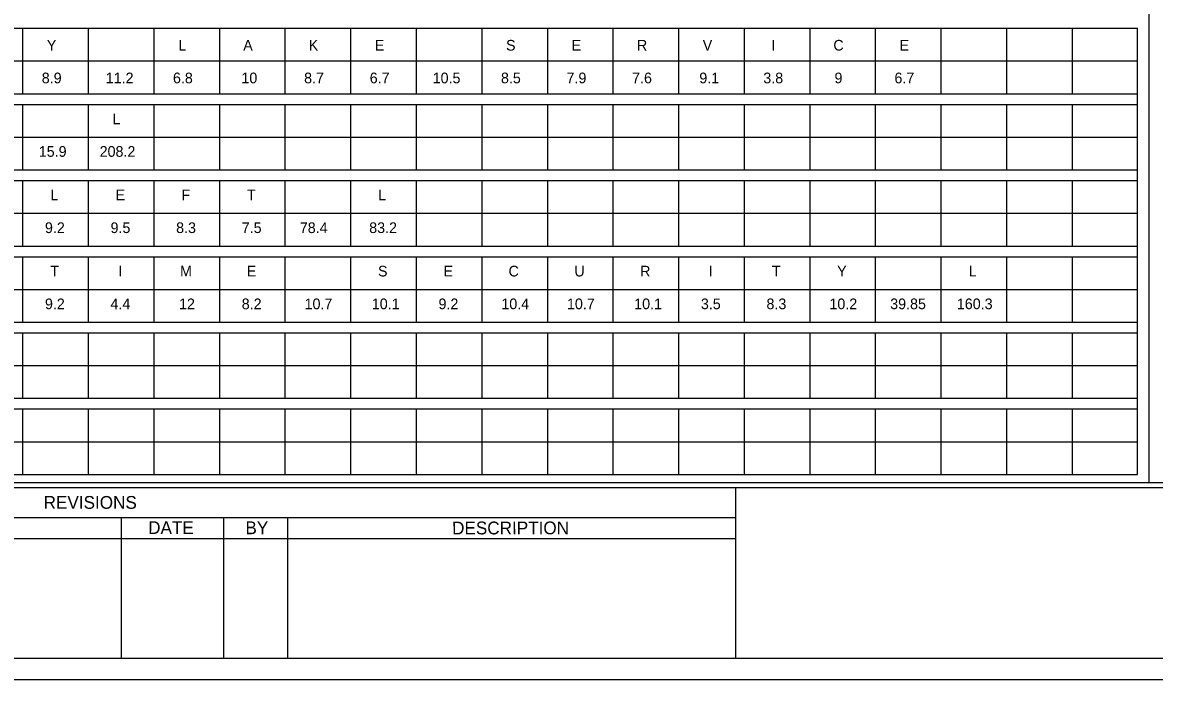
# Model space of a CAD drawing. Extents: x 17890071 to 17890754, y 17897628 to 17897992.
# Drawn here: x 17890100.2 to 17890152.1, y 17897766.7 to 17897796.9 of the extents above; entities that cross this region are included whole.
import ezdxf

# ---------------------------------------------------------------- set-up
doc = ezdxf.new("R2010")
doc.units = 0
for name, color, linetype in [('GSSign', 7, 'Continuous'), ('PlotBorder_dp', 7, 'Continuous'), ('SheetBorder_dp', 7, 'Continuous'), ('SheetLines_dp', 7, 'Continuous'), ('SheetLinesMisc2_dp', 7, 'Continuous'), ('TextMisc', 7, 'Continuous')]:
    doc.layers.add(name, color=color, linetype=linetype)

msp = doc.modelspace()

# ---------------------------------------------------------------- linework, layer by layer
at = {"layer": 'PlotBorder_dp'}
msp.add_lwpolyline([(17890071.13, 17897766.734), (17890232.646, 17897766.734), (17890232.646, 17897870.495), (17890071.13, 17897870.495)], close=True, dxfattribs=at)
at = {"layer": 'SheetBorder_dp'}
for p, q in [((17890076.514, 17897775.543), (17890227.262, 17897775.543)), ((17890076.514, 17897767.712), (17890227.262, 17897767.712))]:
    msp.add_line(p, q, dxfattribs=at)
at = {"layer": 'SheetLines_dp'}
for p, q in [((17890132.897, 17897775.543), (17890132.897, 17897767.712)), ((17890076.514, 17897774.173), (17890132.897, 17897774.173)), ((17890104.706, 17897774.173), (17890104.706, 17897767.712)), ((17890109.404, 17897774.173), (17890109.404, 17897767.712)), ((17890112.341, 17897774.173), (17890112.341, 17897767.712)), ((17890076.514, 17897773.194), (17890132.897, 17897773.194))]:
    msp.add_line(p, q, dxfattribs=at)
at = {"layer": 'SheetLinesMisc2_dp'}
for p, q in [((17890151.871, 17897869.435), (17890151.871, 17897775.777)), ((17890077.364, 17897796.631), (17890151.359, 17897796.631)), ((17890100.188, 17897796.631), (17890100.188, 17897793.624)), ((17890103.198, 17897796.631), (17890103.198, 17897793.624)), ((17890106.208, 17897796.631), (17890106.208, 17897793.624)), ((17890109.218, 17897796.631), (17890109.218, 17897793.624)), ((17890112.228, 17897796.631), (17890112.228, 17897793.624)), ((17890115.238, 17897796.631), (17890115.238, 17897793.624)), ((17890118.248, 17897796.631), (17890118.248, 17897793.624)), ((17890121.258, 17897796.631), (17890121.258, 17897793.624)), ((17890124.269, 17897796.631), (17890124.269, 17897793.624)), ((17890127.279, 17897796.631), (17890127.279, 17897793.624)), ((17890130.289, 17897796.631), (17890130.289, 17897793.624)), ((17890133.299, 17897796.631), (17890133.299, 17897793.624)), ((17890136.309, 17897796.631), (17890136.309, 17897793.624)), ((17890139.319, 17897796.631), (17890139.319, 17897793.624)), ((17890142.329, 17897796.631), (17890142.329, 17897793.624)), ((17890145.339, 17897796.631), (17890145.339, 17897793.624)), ((17890148.35, 17897796.631), (17890148.35, 17897793.624)), ((17890151.359, 17897776.142), (17890151.359, 17897796.631)), ((17890077.364, 17897795.129), (17890151.359, 17897795.129)), ((17890077.364, 17897793.624), (17890151.359, 17897793.624)), ((17890077.364, 17897793.134), (17890151.359, 17897793.134)), ((17890100.188, 17897793.134), (17890100.188, 17897790.128)), ((17890103.198, 17897793.134), (17890103.198, 17897790.128)), ((17890106.208, 17897793.134), (17890106.208, 17897790.128)), ((17890109.218, 17897793.134), (17890109.218, 17897790.128)), ((17890112.228, 17897793.134), (17890112.228, 17897790.128)), ((17890115.238, 17897793.134), (17890115.238, 17897790.128)), ((17890118.248, 17897793.134), (17890118.248, 17897790.128)), ((17890121.258, 17897793.134), (17890121.258, 17897790.128)), ((17890124.269, 17897793.134), (17890124.269, 17897790.128)), ((17890127.279, 17897793.134), (17890127.279, 17897790.128)), ((17890130.289, 17897793.134), (17890130.289, 17897790.128)), ((17890133.299, 17897793.134), (17890133.299, 17897790.128)), ((17890136.309, 17897793.134), (17890136.309, 17897790.128)), ((17890139.319, 17897793.134), (17890139.319, 17897790.128)), ((17890142.329, 17897793.134), (17890142.329, 17897790.128)), ((17890145.339, 17897793.134), (17890145.339, 17897790.128)), ((17890148.35, 17897793.134), (17890148.35, 17897790.128)), ((17890077.364, 17897791.631), (17890151.359, 17897791.631)), ((17890077.364, 17897790.128), (17890151.359, 17897790.128)), ((17890077.364, 17897789.637), (17890151.359, 17897789.637)), ((17890100.188, 17897789.637), (17890100.188, 17897786.631)), ((17890103.198, 17897789.637), (17890103.198, 17897786.631)), ((17890106.208, 17897789.637), (17890106.208, 17897786.631)), ((17890109.218, 17897789.637), (17890109.218, 17897786.631)), ((17890112.228, 17897789.637), (17890112.228, 17897786.631)), ((17890115.238, 17897789.637), (17890115.238, 17897786.631)), ((17890118.248, 17897789.637), (17890118.248, 17897786.631)), ((17890121.258, 17897789.637), (17890121.258, 17897786.631)), ((17890124.269, 17897789.637), (17890124.269, 17897786.631)), ((17890127.279, 17897789.637), (17890127.279, 17897786.631)), ((17890130.289, 17897789.637), (17890130.289, 17897786.631)), ((17890133.299, 17897789.637), (17890133.299, 17897786.631)), ((17890136.309, 17897789.637), (17890136.309, 17897786.631)), ((17890139.319, 17897789.637), (17890139.319, 17897786.631)), ((17890142.329, 17897789.637), (17890142.329, 17897786.631)), ((17890145.339, 17897789.637), (17890145.339, 17897786.631)), ((17890148.35, 17897789.637), (17890148.35, 17897786.631)), ((17890077.364, 17897788.135), (17890151.359, 17897788.135)), ((17890077.364, 17897786.631), (17890151.359, 17897786.631)), ((17890077.364, 17897786.141), (17890151.359, 17897786.141)), ((17890100.188, 17897786.141), (17890100.188, 17897783.135)), ((17890103.198, 17897786.141), (17890103.198, 17897783.135)), ((17890106.208, 17897786.141), (17890106.208, 17897783.135)), ((17890109.218, 17897786.141), (17890109.218, 17897783.135)), ((17890112.228, 17897786.141), (17890112.228, 17897783.135)), ((17890115.238, 17897786.141), (17890115.238, 17897783.135)), ((17890118.248, 17897786.141), (17890118.248, 17897783.135)), ((17890121.258, 17897786.141), (17890121.258, 17897783.135)), ((17890124.269, 17897786.141), (17890124.269, 17897783.135)), ((17890127.279, 17897786.141), (17890127.279, 17897783.135)), ((17890130.289, 17897786.141), (17890130.289, 17897783.135)), ((17890133.299, 17897786.141), (17890133.299, 17897783.135)), ((17890136.309, 17897786.141), (17890136.309, 17897783.135)), ((17890139.319, 17897786.141), (17890139.319, 17897783.135)), ((17890142.329, 17897786.141), (17890142.329, 17897783.135)), ((17890145.339, 17897786.141), (17890145.339, 17897783.135)), ((17890148.35, 17897786.141), (17890148.35, 17897783.135)), ((17890077.364, 17897784.639), (17890151.359, 17897784.639)), ((17890077.364, 17897783.135), (17890151.359, 17897783.135)), ((17890077.364, 17897782.644), (17890151.359, 17897782.644)), ((17890100.188, 17897782.644), (17890100.188, 17897779.638)), ((17890103.198, 17897782.644), (17890103.198, 17897779.638)), ((17890106.208, 17897782.644), (17890106.208, 17897779.638)), ((17890109.218, 17897782.644), (17890109.218, 17897779.638)), ((17890112.228, 17897782.644), (17890112.228, 17897779.638)), ((17890115.238, 17897782.644), (17890115.238, 17897779.638)), ((17890118.248, 17897782.644), (17890118.248, 17897779.638)), ((17890121.258, 17897782.644), (17890121.258, 17897779.638)), ((17890124.269, 17897782.644), (17890124.269, 17897779.638)), ((17890127.279, 17897782.644), (17890127.279, 17897779.638)), ((17890130.289, 17897782.644), (17890130.289, 17897779.638)), ((17890133.299, 17897782.644), (17890133.299, 17897779.638)), ((17890136.309, 17897782.644), (17890136.309, 17897779.638)), ((17890139.319, 17897782.644), (17890139.319, 17897779.638)), ((17890142.329, 17897782.644), (17890142.329, 17897779.638)), ((17890145.339, 17897782.644), (17890145.339, 17897779.638)), ((17890148.35, 17897782.644), (17890148.35, 17897779.638)), ((17890077.364, 17897781.141), (17890151.359, 17897781.141)), ((17890077.364, 17897779.638), (17890151.359, 17897779.638)), ((17890077.364, 17897779.148), (17890151.359, 17897779.148)), ((17890100.188, 17897779.148), (17890100.188, 17897776.142)), ((17890103.198, 17897779.148), (17890103.198, 17897776.142)), ((17890106.208, 17897779.148), (17890106.208, 17897776.142)), ((17890109.218, 17897779.148), (17890109.218, 17897776.142)), ((17890112.228, 17897779.148), (17890112.228, 17897776.142)), ((17890115.238, 17897779.148), (17890115.238, 17897776.142)), ((17890118.248, 17897779.148), (17890118.248, 17897776.142)), ((17890121.258, 17897779.148), (17890121.258, 17897776.142)), ((17890124.269, 17897779.148), (17890124.269, 17897776.142)), ((17890127.279, 17897779.148), (17890127.279, 17897776.142)), ((17890130.289, 17897779.148), (17890130.289, 17897776.142)), ((17890133.299, 17897779.148), (17890133.299, 17897776.142)), ((17890136.309, 17897779.148), (17890136.309, 17897776.142)), ((17890139.319, 17897779.148), (17890139.319, 17897776.142)), ((17890142.329, 17897779.148), (17890142.329, 17897776.142)), ((17890145.339, 17897779.148), (17890145.339, 17897776.142)), ((17890148.35, 17897779.148), (17890148.35, 17897776.142)), ((17890077.364, 17897777.645), (17890151.359, 17897777.645)), ((17890077.364, 17897776.142), (17890151.359, 17897776.142)), ((17890076.643, 17897775.777), (17890227.099, 17897775.777))]:
    msp.add_line(p, q, dxfattribs=at)

# ---------------------------------------------------------------- texts
at = {"layer": 'GSSign'}
for s, height, p in [('Y', 0.49, (17890101.298, 17897795.604)), ('L', 0.49, (17890107.335, 17897795.604)), ('A', 0.49, (17890110.312, 17897795.604)), ('K', 0.49, (17890113.317, 17897795.604)), ('E', 0.49, (17890116.351, 17897795.604)), ('S', 0.49, (17890122.373, 17897795.604)), ('E', 0.49, (17890125.382, 17897795.604)), ('R', 0.49, (17890128.381, 17897795.604)), ('V', 0.49, (17890131.401, 17897795.604)), ('I', 0.49, (17890134.545, 17897795.604)), ('C', 0.49, (17890137.396, 17897795.604)), ('E', 0.49, (17890140.434, 17897795.604)), ('8.9', 0.4902, (17890101.066, 17897794.102)), ('11.2', 0.4902, (17890104.001, 17897794.102)), ('6.8', 0.4902, (17890107.087, 17897794.102)), ('10', 0.4902, (17890110.228, 17897794.102)), ('8.7', 0.4902, (17890113.106, 17897794.102)), ('6.7', 0.4902, (17890116.117, 17897794.102)), ('10.5', 0.4902, (17890119.006, 17897794.102)), ('8.5', 0.4902, (17890122.14, 17897794.102)), ('7.9', 0.4902, (17890125.149, 17897794.102)), ('7.6', 0.4902, (17890128.158, 17897794.102)), ('9.1', 0.4902, (17890131.244, 17897794.102)), ('3.8', 0.4902, (17890134.18, 17897794.102)), ('9', 0.49, (17890137.447, 17897794.102)), ('6.7', 0.4902, (17890140.2, 17897794.102)), ('L', 0.49, (17890104.317, 17897792.225)), ('15.9', 0.4902, (17890100.929, 17897790.727)), ('208.2', 0.4902, (17890103.722, 17897790.727)), ('L', 0.49, (17890101.46, 17897788.729)), ('E', 0.49, (17890104.455, 17897788.729)), ('F', 0.49, (17890107.474, 17897788.729)), ('T', 0.49, (17890110.488, 17897788.729)), ('L', 0.49, (17890116.512, 17897788.729)), ('9.2', 0.4902, (17890101.212, 17897787.226)), ('9.5', 0.4902, (17890104.223, 17897787.226)), ('8.3', 0.4902, (17890107.233, 17897787.226)), ('7.5', 0.4902, (17890110.244, 17897787.226)), ('78.4', 0.4902, (17890112.909, 17897787.226)), ('83.2', 0.4902, (17890116.093, 17897787.226)), ('T', 0.49, (17890101.457, 17897785.233)), ('I', 0.49, (17890104.587, 17897785.233)), ('M', 0.49, (17890107.41, 17897785.233)), ('E', 0.49, (17890110.475, 17897785.233)), ('S', 0.49, (17890116.497, 17897785.233)), ('E', 0.49, (17890119.507, 17897785.233)), ('C', 0.49, (17890122.489, 17897785.233)), ('U', 0.49, (17890125.508, 17897785.233)), ('R', 0.49, (17890128.526, 17897785.233)), ('I', 0.49, (17890131.68, 17897785.233)), ('T', 0.49, (17890134.571, 17897785.233)), ('Y', 0.49, (17890137.567, 17897785.233)), ('L', 0.49, (17890143.605, 17897785.233)), ('9.2', 0.4902, (17890101.212, 17897783.73)), ('4.4', 0.4902, (17890104.22, 17897783.73)), ('12', 0.4902, (17890107.365, 17897783.73)), ('8.2', 0.4902, (17890110.243, 17897783.73)), ('10.7', 0.4902, (17890113.128, 17897783.73)), ('10.1', 0.4902, (17890116.214, 17897783.73)), ('9.2', 0.4902, (17890119.274, 17897783.73)), ('10.4', 0.4902, (17890122.158, 17897783.73)), ('10.7', 0.4902, (17890125.169, 17897783.73)), ('10.1', 0.4902, (17890128.256, 17897783.73)), ('3.5', 0.4902, (17890131.316, 17897783.73)), ('8.3', 0.4902, (17890134.326, 17897783.73)), ('10.2', 0.4902, (17890137.213, 17897783.73)), ('39.85', 0.4902, (17890140.003, 17897783.73)), ('160.3', 0.4902, (17890143.063, 17897783.73))]:
    msp.add_text(s, height=height, dxfattribs=at).set_placement(p)
at = {"layer": 'TextMisc'}
for s, p in [('REVISIONS', (17890101.152, 17897774.565)), ('BY', (17890110.413, 17897773.4))]:
    msp.add_text(s, height=0.5873, dxfattribs=at).set_placement(p)
for s, height, rotation, p in [('DATE', 0.5873, 359.8693, (17890105.949, 17897773.409)), ('DESCRIPTION', 0.58721, 0.0498, (17890119.898, 17897773.39))]:
    msp.add_text(s, height=height, rotation=rotation, dxfattribs=at).set_placement(p)

doc.saveas('drawing.dxf')
